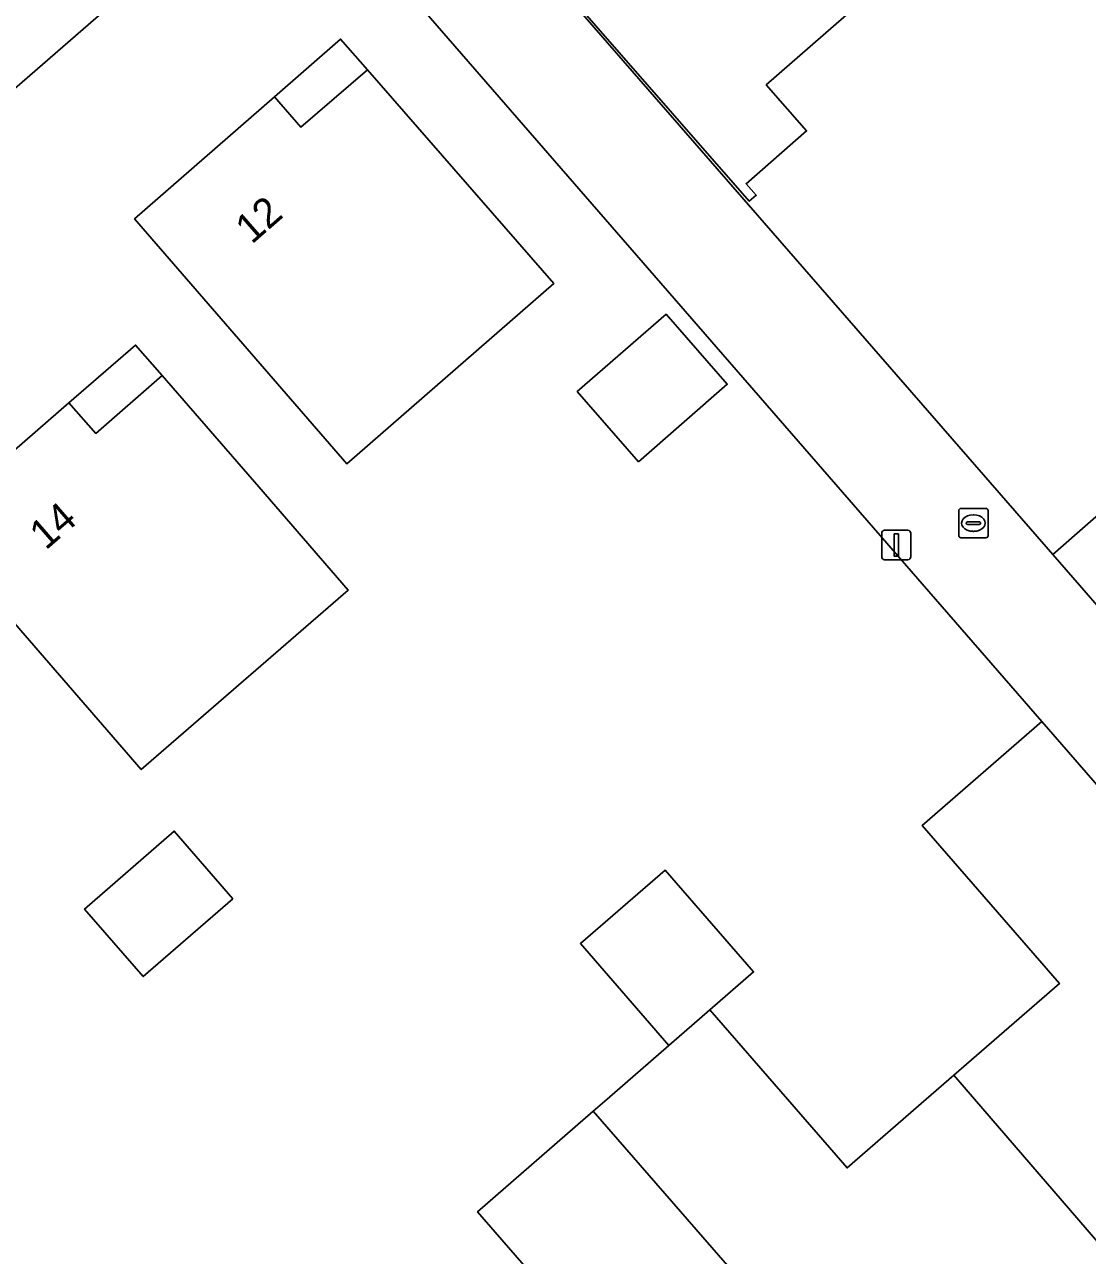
# Model space of a CAD drawing. Extents: x 155887 to 156869, y 383880 to 384678.
# Drawn here: x 156187.92 to 156224.02, y 384244.7 to 384286.49 of the extents above; entities that cross this region are included whole.
import ezdxf

# ---------------------------------------------------------------- set-up
doc = ezdxf.new("R2010")
doc.units = 0
for name, color, linetype in [('IMGEO_Erf', 7, 'Continuous'), ('IMGEO_Kolk', 7, 'Continuous'), ('IMGEO_Lichtmast', 7, 'Continuous'), ('IMGEO_Pand', 7, 'Continuous'), ('IMGEO_Pand_nummerreeks', 7, 'Continuous'), ('IMGEO_Pand_overbouw', 7, 'Continuous'), ('IMGEO_Rijbaan_lokaal_open', 7, 'Continuous'), ('IMGEO_Voetpad_open', 7, 'Continuous')]:
    doc.layers.add(name, color=color, linetype=linetype)

msp = doc.modelspace()

# ---------------------------------------------------------------- linework, layer by layer
at = {"layer": 'IMGEO_Erf'}
for points in [[(156245.448, 384334.593), (156199.823, 384294.964), (156222.851, 384268.495), (156226.866, 384272.016)], [(156207.972, 384240.812), (156203.309, 384246.179), (156207.24, 384249.593), (156207.708, 384250), (156209.809, 384251.825), (156206.803, 384255.285), (156209.676, 384257.781), (156212.682, 384254.321), (156211.198, 384253.032), (156213.833, 384250), (156215.861, 384247.665), (156218.549, 384250), (156219.485, 384250.813), (156223.071, 384253.928), (156218.408, 384259.295), (156222.476, 384262.828), (156196.813, 384292.349), (156151.225, 384252.74)]]:
    msp.add_lwpolyline(points, dxfattribs=at)
for points in [[(156220.122, 384290.065), (156219.873, 384289.847), (156219.623, 384290.133), (156213.113, 384284.448), (156214.481, 384282.881), (156212.431, 384281.091), (156212.772, 384280.699), (156212.538, 384280.495), (156204.722, 384289.444), (156206.77, 384291.232), (156209.31, 384293.45), (156208.625, 384294.233), (156208.346, 384293.989), (156208.128, 384294.237), (156212.892, 384298.368)], [(156191.658, 384279.894), (156196.411, 384284.042), (156197.309, 384283.007), (156199.566, 384284.961), (156205.897, 384277.701), (156198.87, 384271.573)], [(156208.77, 384271.649), (156206.694, 384274.029), (156209.711, 384276.66), (156211.786, 384274.28)], [(156187.944, 384265.743), (156184.669, 384269.521), (156189.429, 384273.646), (156190.338, 384272.608), (156192.596, 384274.572), (156195.874, 384270.796), (156198.915, 384267.29), (156191.883, 384261.196)], [(156195.001, 384256.808), (156191.955, 384254.163), (156189.962, 384256.457), (156193.008, 384259.103)]]:
    msp.add_lwpolyline(points, close=True, dxfattribs=at)
at = {"layer": 'IMGEO_Kolk'}
for p, q in [((156219.724, 384270.065), (156220.576, 384270.065)), ((156219.649, 384269.139), (156219.649, 384269.991)), ((156219.951, 384269.608), (156220.349, 384269.608)), ((156220.137, 384269.845), (156220.162, 384269.845)), ((156220.65, 384269.991), (156220.65, 384269.139)), ((156219.908, 384269.559), (156219.908, 384269.571)), ((156220.346, 384269.522), (156219.948, 384269.522)), ((156220.16, 384269.285), (156220.135, 384269.285)), ((156220.392, 384269.571), (156220.392, 384269.559)), ((156220.576, 384269.065), (156219.724, 384269.065))]:
    msp.add_line(p, q, dxfattribs=at)
for points in [[(156219.724, 384270.065), (156220.576, 384270.065)], [(156219.649, 384269.139), (156219.649, 384269.991)], [(156220.65, 384269.991), (156220.65, 384269.139)], [(156220.576, 384269.065), (156219.724, 384269.065)]]:
    msp.add_lwpolyline(points, dxfattribs=at)
for centre, radius, start, end in [((156219.726, 384269.989), 0.0765, 91.552, 178.448), ((156219.726, 384269.989), 0.0765, 91.552, 178.448), ((156220.574, 384269.989), 0.0765, 1.552, 88.448), ((156220.574, 384269.989), 0.0765, 1.552, 88.448), ((156219.948, 384269.568), 0.0403, 85.8775, 175.7526), ((156220.353, 384269.57), 0.0386, 1.7309, 96.639), ((156219.945, 384269.558), 0.0366, 178.938, 274.7102), ((156220.349, 384269.565), 0.043, 264.8664, 352.4533), ((156219.726, 384269.141), 0.0765, 181.552, 268.448), ((156219.726, 384269.141), 0.0765, 181.552, 268.448), ((156220.574, 384269.141), 0.0765, 271.552, 358.448), ((156220.574, 384269.141), 0.0765, 271.552, 358.448)]:
    msp.add_arc(centre, radius, start, end, dxfattribs=at)
for centre, major_axis, ratio, start_param, end_param in [((156220.136, 384269.565), (-0.387, 0.002), 0.722429, 4.712389, 7.853982), ((156220.161, 384269.565), (-0.39, 0.002), 0.717154, 1.570796, 4.712389)]:
    msp.add_ellipse(centre, major_axis=major_axis, ratio=ratio, start_param=start_param, end_param=end_param, dxfattribs=at)
at = {"layer": 'IMGEO_Lichtmast'}
for p, q in [((156217.034, 384268.42), (156217.034, 384269.22)), ((156217.034, 384269.22), (156217.034, 384268.42)), ((156217.134, 384269.32), (156217.924, 384269.32)), ((156217.924, 384269.32), (156217.134, 384269.32)), ((156218.024, 384269.22), (156218.024, 384268.42)), ((156218.024, 384268.42), (156218.024, 384269.22)), ((156217.924, 384268.32), (156217.134, 384268.32)), ((156217.134, 384268.32), (156217.924, 384268.32))]:
    msp.add_line(p, q, dxfattribs=at)
msp.add_lwpolyline([(156217.454, 384269.195), (156217.604, 384269.195), (156217.604, 384268.445), (156217.454, 384268.445), (156217.454, 384269.195)], dxfattribs=at)
for centre, start, end in [((156217.134, 384269.22), 90, 180), ((156217.134, 384269.22), 90, 180), ((156217.924, 384269.22), 0, 90), ((156217.924, 384269.22), 360, 90), ((156217.134, 384268.42), 180, 270), ((156217.134, 384268.42), 180, 270), ((156217.924, 384268.42), 270, 0), ((156217.924, 384268.42), 270, 0)]:
    msp.add_arc(centre, 0.1, start, end, dxfattribs=at)
at = {"layer": 'IMGEO_Pand'}
for points in [[(156206.77, 384291.232), (156204.722, 384289.444), (156212.538, 384280.495), (156212.772, 384280.699), (156212.431, 384281.091), (156214.481, 384282.881), (156213.113, 384284.448), (156219.623, 384290.133), (156219.873, 384289.847), (156220.122, 384290.065), (156212.892, 384298.368), (156208.128, 384294.237), (156208.346, 384293.989), (156208.625, 384294.233), (156209.31, 384293.45)], [(156196.411, 384284.042), (156191.658, 384279.894), (156198.87, 384271.573), (156205.897, 384277.701), (156199.566, 384284.961), (156197.309, 384283.007)], [(156208.77, 384271.649), (156211.786, 384274.28), (156209.711, 384276.66), (156206.694, 384274.029)], [(156192.596, 384274.572), (156190.338, 384272.608), (156189.429, 384273.646), (156184.669, 384269.521), (156187.944, 384265.743), (156191.883, 384261.196), (156198.915, 384267.29), (156195.874, 384270.796)], [(156229.535, 384269.017), (156227.303, 384271.525), (156226.866, 384272.016), (156222.851, 384268.495), (156225.482, 384265.463)], [(156219.485, 384250.813), (156220.187, 384250), (156226.713, 384242.443), (156226.823, 384242.539), (156226.226, 384243.223), (156230.755, 384247.157), (156235.602, 384241.577), (156234.659, 384240.759), (156234.822, 384240.57), (156238.811, 384244.035), (156233.627, 384250), (156222.476, 384262.828), (156218.408, 384259.295), (156223.071, 384253.928)], [(156195.001, 384256.808), (156193.008, 384259.103), (156189.962, 384256.457), (156191.955, 384254.163)], [(156206.803, 384255.285), (156209.809, 384251.825), (156211.198, 384253.032), (156212.682, 384254.321), (156209.676, 384257.781)], [(156220.187, 384250), (156219.485, 384250.813), (156218.549, 384250), (156215.861, 384247.665), (156213.833, 384250), (156211.198, 384253.032), (156209.809, 384251.825), (156207.708, 384250), (156207.24, 384249.593), (156223.587, 384230.812), (156227.423, 384234.143), (156227.26, 384234.332), (156226.315, 384233.511), (156221.469, 384239.091), (156225.999, 384243.026), (156226.594, 384242.34), (156226.713, 384242.443)], [(156207.24, 384249.593), (156203.309, 384246.179), (156207.972, 384240.812), (156204.364, 384237.678), (156211.615, 384229.33), (156211.723, 384229.424), (156211.126, 384230.108), (156215.655, 384234.042), (156220.501, 384228.462), (156219.559, 384227.644), (156219.722, 384227.455), (156223.587, 384230.812)]]:
    msp.add_lwpolyline(points, close=True, dxfattribs=at)
at = {"layer": 'IMGEO_Pand_overbouw'}
for points in [[(156197.309, 384283.007), (156199.566, 384284.961), (156198.658, 384286.003), (156196.411, 384284.042)], [(156189.429, 384273.646), (156190.338, 384272.608), (156192.596, 384274.572), (156191.695, 384275.61)]]:
    msp.add_lwpolyline(points, close=True, dxfattribs=at)
at = {"layer": 'IMGEO_Rijbaan_lokaal_open'}
msp.add_lwpolyline([(156238.931, 384250), (156225.482, 384265.463), (156222.851, 384268.495), (156199.823, 384294.964), (156196.813, 384292.349), (156222.476, 384262.828), (156233.627, 384250), (156238.811, 384244.035), (156239.812, 384242.902), (156242.8, 384239.463), (156245.758, 384242.109), (156242.787, 384245.529), (156241.836, 384246.66)], close=True, dxfattribs=at)
at = {"layer": 'IMGEO_Voetpad_open'}
msp.add_lwpolyline([(156145.532, 384247.791), (156148.072, 384250), (156149.771, 384251.478), (156151.225, 384252.74), (156196.813, 384292.349)], dxfattribs=at)

# ---------------------------------------------------------------- texts
at = {"layer": 'IMGEO_Pand_nummerreeks'}
for s, rotation, p in [('12', 41.1116, (156195.635, 384279.011)), ('14', 40.9121, (156188.641, 384268.623))]:
    msp.add_text(s, height=1, rotation=rotation, dxfattribs=at).set_placement(p)

doc.saveas('drawing.dxf')
